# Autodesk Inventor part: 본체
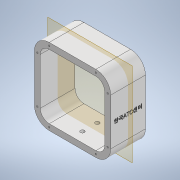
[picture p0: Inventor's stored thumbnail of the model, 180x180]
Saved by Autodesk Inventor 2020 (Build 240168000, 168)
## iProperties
Created: 2016-12
Part Number: 본체
Material: 알루미늄 6061
Document SubType Name: Modeling
Designer: mduedu
Density: 2.71 g/cm^3
Mass: 1192.15 g
Surface Area: 887.138 cm^2
Volume: 439.908 cm^3
Appearance: 기본값
Author: mduedu
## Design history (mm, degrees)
sketch "스케치1"
  geometry: L1 (-54, 50)-(-54, -44); L2 (-24, 80)-(70, 80); L3 (100, 50)-(100, -44); L4 (70, -74)-(-24, -74); A1 r 30 centre (-24, -44) between (-54, -44) and (-24, -74); A2 r 30 centre (70, 50) between (100, 50) and (70, 80); A3 r 30 centre (70, -44) between (70, -74) and (100, -44); A4 r 30 centre (-24, 50) between (-24, 80) and (-54, 50); 1 further point
  constraints: 8 end point, 8 point on circle, 8 tangent, 4 centre point, 3 equal radius, 2 perpendicular, 1 horizontal, 1 vertical
  dimensions: "d83" = 30 radius of A2; "d84" = 100 distance from line of L3 point (0, 0); "d85" = 154 distance between parallel lines of L4 L2; "d87" = 80 distance from line of point (0, 0) L2
extrude "돌출1" new body sketch "스케치1" stored distance "d3" = 70; taper "d4" = 0 deg
feature "쉘1" dims "d5" = 12
sketch "스케치10"
  geometry: 2 further points
  constraints: 1 coincident, 1 other
feature "엠보싱1" sketch "스케치10" dims "d61" = 0.5, "d62" = 0
sketch "스케치11"
  geometry: L1 (-42, -44)-(-42, 50) reference; L2 (-24, 68)-(70, 68) reference; L3 (88, 50)-(88, -44) reference; L4 (70, -62)-(-24, -62) reference; L5 (-24, -74)-(70, -74) reference; L6 (100, -44)-(100, 50) reference; L7 (70, 80)-(-24, 80) reference; L8 (-54, 50)-(-54, -44) reference; L9 (-24, 74)-(70, 74); L10 (94, 50)-(94, -44); L11 (70, -68)-(-24, -68); L12 (-48, -44)-(-48, 50); A1 r 18 centre (-24, -44) between (-42, -44) and (-24, -62) reference; A2 r 18 centre (-24, 50) between (-24, 68) and (-42, 50) reference; A3 r 18 centre (70, 50) between (88, 50) and (70, 68) reference; A4 r 18 centre (70, -44) between (70, -62) and (88, -44) reference; A5 r 30 centre (-24, -44) between (-54, -44) and (-24, -74) reference; A6 r 30 centre (70, -44) between (70, -74) and (100, -44) reference; A7 r 30 centre (70, 50) between (100, 50) and (70, 80) reference; A8 r 30 centre (-24, 50) between (-24, 80) and (-54, 50) reference; A9 r 24 centre (70, 50) between (94, 50) and (70, 74); A10 r 24 centre (70, -44) between (70, -68) and (94, -44); A11 r 24 centre (-24, -44) between (-48, -44) and (-24, -68); A12 r 24 centre (-24, 50) between (-24, 74) and (-48, 50); 8 further points
  constraints: 8 coincident, 8 end point, 8 point on circle, 4 centre point, 7 other
  dimensions: "d90" = 6 distance between parallel lines of L9 L7
hole "구멍3" sketch "스케치11" at (-24, 74), (-48, 50), (-48, -44), (-24, -68), (70, -68), (94, -44), (94, 50), (70, 74) diameter "d63" = 3.242; stored, may be unused: countersink angle "d67" = 90 deg, drill point angle "d69" = 120 deg; dims "d64" = 8.6, "d65" = 4, "d66" = 2, "d68" = 10.6
sketch "스케치12"
  geometry: L1 (24, -62)-(-70, -62) reference; L2 (-88, -44)-(-88, 50) reference; L3 (-70, 68)-(24, 68) reference; L4 (42, 50)-(42, -44) reference; L5 (54, -44)-(54, 50) reference; L6 (24, 80)-(-70, 80) reference; L7 (-100, 50)-(-100, -44) reference; L8 (-70, -74)-(24, -74) reference; L9 (-70, 74)-(24, 74); L10 (48, 50)-(48, -44); L11 (24, -68)-(-70, -68); L12 (-94, -44)-(-94, 50); A1 r 18 centre (24, -44) between (24, -62) and (42, -44) reference; A2 r 18 centre (-70, -44) between (-88, -44) and (-70, -62) reference; A3 r 18 centre (-70, 50) between (-70, 68) and (-88, 50) reference; A4 r 18 centre (24, 50) between (42, 50) and (24, 68) reference; A5 r 30 centre (24, -44) between (24, -74) and (54, -44) reference; A6 r 30 centre (24, 50) between (54, 50) and (24, 80) reference; A7 r 30 centre (-70, 50) between (-70, 80) and (-100, 50) reference; A8 r 30 centre (-70, -44) between (-100, -44) and (-70, -74) reference; A9 r 24 centre (24, 50) between (48, 50) and (24, 74); A10 r 24 centre (24, -44) between (24, -68) and (48, -44); A11 r 24 centre (-70, -44) between (-94, -44) and (-70, -68); A12 r 24 centre (-70, 50) between (-70, 74) and (-94, 50); 8 further points
  constraints: 8 coincident, 8 end point, 8 point on circle, 4 centre point, 7 other
  dimensions: "d91" = 6 distance between parallel lines of L9 L6
hole "구멍5" sketch "스케치12" at (-70, 74), (-94, 50), (-94, -44), (-70, -68), (24, -68), (48, -44), (48, 50), (24, 74) diameter "d70" = 3.242; stored, may be unused: countersink angle "d74" = 90 deg, drill point angle "d76" = 120 deg; dims "d71" = 8.6, "d72" = 4, "d73" = 2, "d75" = 10.6
sketch "스케치15"
  geometry: L1 (154.8, -35)-(-60.8, -35) reference; L2 (94, 0)-(0, 0) reference; L3 (0, -70)-(94, -70) reference; L4 (47, 0)-(47, -70); C1 r 4 at (47, -20); C2 r 4 at (47, -50); 1 further point
  constraints: 2 centre point, 2 end point, 2 midpoint, 1 point on line, 1 symmetric about line, 1 other
  dimensions: "d92" = 8 diameter of C1; "d93" = 15 distance from line of C1.centre L1
extrude "돌출6" cut sketch "스케치15" extent not by distance; stored distance "d94" = 10; taper "d95" = 0 deg
node "작업 평면3"
node "솔리드1"
node "투영된 루프3"
node "투영된 루프4"
